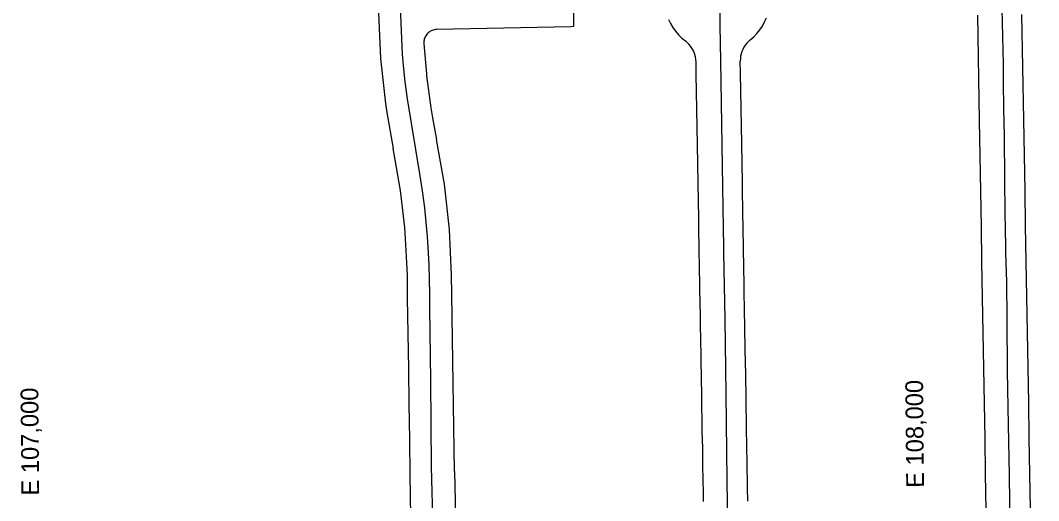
# Model space of a CAD drawing. Extents: x -2233 to 187241, y 4582 to 150524.
# Drawn here: x 106970 to 108120, y 60052 to 60594 of the extents above; entities that cross this region are included whole.
import ezdxf

# ---------------------------------------------------------------- set-up
doc = ezdxf.new("R2010")
doc.units = 0
for name, color, linetype in [('GE_X_CL_2000', 7, 'Continuous'), ('GRID', 7, 'Continuous'), ('RW_X_Fee_RW', 7, 'Continuous')]:
    doc.layers.add(name, color=color, linetype=linetype)

msp = doc.modelspace()

# ---------------------------------------------------------------- linework, layer by layer
at = {"layer": 'GE_X_CL_2000'}
for points in [[(107760, 60619.2), (107760.2, 60588.5), (107761, 60548.6), (107761.2, 60524.8), (107762, 60477), (107763.3, 60382.6), (107764.1, 60338), (107764.2, 60331.5), (107765.6, 60257.1), (107767, 60172.1), (107768, 60074.5), (107769.6, 59968.1), (107770.4, 59911.1), (107771, 59857.5), (107772.8, 59767.8), (107774, 59666), (107775.8, 59576.6), (107776.6, 59504.9), (107777.4, 59464.4)], [(108078.3, 60624.1), (108079.2, 60592.1), (108080.2, 60544.6), (108080.4, 60524.8), (108080.8, 60494.9), (108081.4, 60464.1), (108081.8, 60414), (108082.2, 60377.1), (108082.8, 60338.8), (108083, 60331.5), (108084.2, 60298.8), (108084.5, 60256.2), (108084.9, 60197.9), (108085.9, 60137.2), (108087, 60080.2), (108087.8, 60019)], [(107398.9, 60610.7), (107399.5, 60591.2), (107401.1, 60556.2), (107402.1, 60543.6), (107404.1, 60524.8), (107406.6, 60505.9), (107420.8, 60421.1), (107423.7, 60401.8), (107426.4, 60382.4), (107427.9, 60366.3), (107429.2, 60350.1), (107430.4, 60331.5), (107431.1, 60317.8), (107431.6, 60301.6), (107432, 60285.4), (107432, 60269.2), (107433.2, 60187.4), (107433.8, 60089.6), (107435.7, 60018.7), (107436.7, 59967.1), (107436.9, 59957.5)]]:
    msp.add_lwpolyline(points, dxfattribs=at)
at = {"layer": 'RW_X_Fee_RW'}
for p, q in [((107594, 60637.4), (107594.7, 60587.4)), ((107460.1, 60084.5), (107461.5, 60034.5))]:
    msp.add_line(p, q, dxfattribs=at)
for points in [[(107374.2, 60602.9), (107376.5, 60551.5), (107382.2, 60500.4), (107383.9, 60490.2), (107391, 60449.7)], [(107701.9, 60595.5), (107703.1, 60593), (107704.2, 60590.8), (107706.9, 60586.3), (107709.9, 60582.1), (107713.3, 60578.1), (107717.1, 60574.5), (107721.1, 60571.2)], [(107794.5, 60572.4), (107798.4, 60575.8), (107802, 60579.6), (107805.3, 60583.7), (107808.2, 60588), (107810.7, 60592.6), (107812.9, 60597.4)], [(108070.4, 59503.4), (108068.2, 59633.4), (108067.5, 59674.3), (108066.8, 59715.3), (108066.1, 59756.3), (108065.4, 59797.3), (108064.7, 59838.3), (108064, 59879.3), (108063.3, 59920.3), (108062.6, 59961.3), (108061.9, 60001.3), (108061.2, 60041.3), (108060.5, 60081.3), (108059.8, 60121.3), (108059.2, 60161.3), (108058.5, 60201.3), (108057.8, 60241.3), (108057.1, 60281.3), (108056.4, 60321.3), (108055.7, 60361.2), (108055.1, 60401.2), (108054.4, 60441.2), (108053.7, 60481.2), (108051.6, 60600.3)], [(108120.4, 59504.1), (108118.2, 59634.1), (108117.5, 59675), (108116.8, 59716), (108116.1, 59757), (108115.4, 59798), (108114.7, 59839), (108114, 59880), (108113.3, 59921), (108112.6, 59962), (108111.9, 60002), (108111.2, 60042), (108110.5, 60082), (108109.8, 60122), (108109.2, 60162), (108108.5, 60202), (108107.8, 60242), (108107.1, 60282), (108106.4, 60322), (108105.7, 60362), (108105.1, 60401.9), (108104.4, 60441.9), (108103.7, 60481.9), (108101.6, 60601.2)], [(107440.1, 60584.1), (107438.8, 60584), (107437.5, 60583.8), (107436.2, 60583.5), (107434.9, 60583), (107433.7, 60582.5), (107432.5, 60581.8), (107431.4, 60581.1), (107430.4, 60580.2), (107429.4, 60579.2), (107428.6, 60578.2), (107427.8, 60577.1), (107427.1, 60576), (107426.6, 60574.7), (107426.1, 60573.5), (107425.8, 60572.2), (107425.6, 60570.9), (107425.5, 60569.5), (107425.5, 60568.2)], [(107594.7, 60587.4), (107591.5, 60587.3), (107440.1, 60584.1)], [(107794.5, 60572.4), (107792.4, 60570.6), (107790.5, 60568.6), (107788.8, 60566.5), (107787.3, 60564.2), (107786.1, 60561.7), (107785, 60559.2), (107784.2, 60556.6), (107783.6, 60553.9), (107783.3, 60551.2), (107783.2, 60548.5)], [(107425.5, 60568.2), (107428.4, 60534), (107428.6, 60531.9), (107433.4, 60495.7), (107435.5, 60484.2), (107440, 60459.9)], [(107733.2, 60547.6), (107733, 60550.3), (107732.6, 60553.1), (107732, 60555.7), (107731.1, 60558.3), (107729.9, 60560.8), (107728.6, 60563.2), (107727, 60565.4), (107725.2, 60567.5), (107723.3, 60569.4), (107721.1, 60571.2)], [(107741.7, 60050.4), (107741.5, 60060.4), (107741, 60090.4), (107740.7, 60110.4), (107740.3, 60130.4), (107739.7, 60170.4), (107739, 60210.4), (107738.9, 60215.4), (107738.3, 60250.4), (107738.1, 60260.4), (107737.6, 60290.3), (107737.1, 60320.3), (107736.9, 60330.3), (107736.3, 60365.3), (107736.2, 60370.3), (107735.6, 60410.3), (107734.8, 60453.7), (107733.5, 60533.7), (107733.2, 60547.6)], [(107791.7, 60050.9), (107791.4, 60065.9), (107791.4, 60070.9), (107791, 60090.9), (107790.6, 60115.9), (107790.3, 60130.9), (107789.7, 60168.9), (107789.7, 60170.9), (107789, 60210.9), (107788.8, 60218.9), (107788.3, 60250.9), (107788.1, 60263.9), (107787.6, 60290.9), (107787.1, 60320.9), (107786.9, 60330.9), (107786.3, 60365.9), (107786.2, 60370.9), (107785.6, 60410.9), (107784.8, 60454.9), (107783.4, 60534.9), (107783.2, 60548.5)], [(107456.8, 60306.7), (107454.5, 60358.1), (107448.8, 60409.2), (107440, 60459.9)], [(107406.9, 60306), (107406.2, 60320.5), (107404.6, 60354.2), (107403.9, 60360.4), (107399.3, 60402.2), (107391.8, 60445.3), (107391, 60449.7)], [(107411.2, 60010.5), (107410.2, 60080.5), (107409.6, 60120.5), (107409, 60160.5), (107408.4, 60200.5), (107407.8, 60240.5), (107407.2, 60280.5), (107406.9, 60306)], [(107460.1, 60084.5), (107459.4, 60134.5), (107458.6, 60184.5), (107457.9, 60234.4), (107457.2, 60284.4), (107456.8, 60306.7)]]:
    msp.add_lwpolyline(points, dxfattribs=at)

# ---------------------------------------------------------------- texts
at = {"layer": 'GRID'}
for s, p in [('E 108,000', (107990.8, 60066.1)), ('E 107,000', (106990.8, 60057.4))]:
    msp.add_text(s, height=20, rotation=90.5, dxfattribs=at).set_placement(p)

doc.saveas('drawing.dxf')
